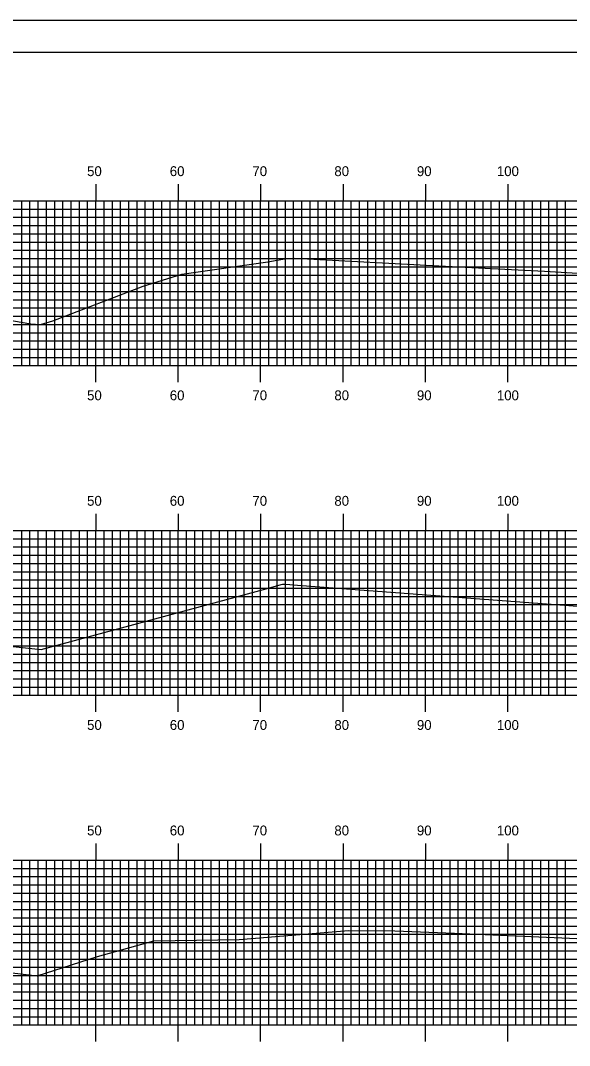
# Model space of a CAD drawing. Extents: x 841388 to 841731, y 363538 to 363758.
# Drawn here: x 841594.7 to 841661.4, y 363633.2 to 363757.6 of the extents above; entities that cross this region are included whole.
import ezdxf

# ---------------------------------------------------------------- set-up
doc = ezdxf.new("R2010")
doc.units = 0
for name, color, linetype in [('BORDER', 7, 'Continuous'), ('H_V ANNOTATION', 7, 'Continuous'), ('MAJOR', 7, 'Continuous'), ('MINOR', 7, 'Continuous'), ('PLOT BOUNDARY', 7, 'Continuous'), ('S_Roadway_Centerline', 7, 'Continuous')]:
    doc.layers.add(name, color=color, linetype=linetype)

msp = doc.modelspace()

# ---------------------------------------------------------------- linework, layer by layer
at = {"layer": 'BORDER'}
msp.add_lwpolyline([(841404.26, 363543.72), (841724.26, 363543.72), (841724.26, 363753.72), (841404.26, 363753.72)], close=True, dxfattribs=at)
at = {"layer": 'MAJOR'}
for p, q in [((841603.86, 363737.73), (841603.86, 363735.72)), ((841613.86, 363737.73), (841613.86, 363735.72)), ((841623.86, 363737.73), (841623.86, 363735.72)), ((841633.86, 363737.73), (841633.86, 363735.72)), ((841643.86, 363737.73), (841643.86, 363735.72)), ((841653.86, 363737.73), (841653.86, 363735.72)), ((841413.86, 363735.72), (841693.86, 363735.72)), ((841413.86, 363735.72), (841693.86, 363735.72)), ((841603.86, 363715.72), (841603.86, 363735.72)), ((841613.86, 363715.72), (841613.86, 363735.72)), ((841623.86, 363715.72), (841623.86, 363735.72)), ((841633.86, 363715.72), (841633.86, 363735.72)), ((841643.86, 363715.72), (841643.86, 363735.72)), ((841653.86, 363715.72), (841653.86, 363735.72)), ((841413.86, 363730.72), (841693.86, 363730.72)), ((841413.86, 363725.72), (841693.86, 363725.72)), ((841413.86, 363720.72), (841693.86, 363720.72)), ((841413.86, 363715.72), (841693.86, 363715.72)), ((841413.86, 363715.72), (841693.86, 363715.72)), ((841603.86, 363713.72), (841603.86, 363715.72)), ((841613.86, 363713.72), (841613.86, 363715.72)), ((841623.86, 363713.72), (841623.86, 363715.72)), ((841633.86, 363713.72), (841633.86, 363715.72)), ((841643.86, 363713.72), (841643.86, 363715.72)), ((841653.86, 363713.72), (841653.86, 363715.72)), ((841603.86, 363697.73), (841603.86, 363695.72)), ((841613.86, 363697.73), (841613.86, 363695.72)), ((841623.86, 363697.73), (841623.86, 363695.72)), ((841633.86, 363697.73), (841633.86, 363695.72)), ((841643.86, 363697.73), (841643.86, 363695.72)), ((841653.86, 363697.73), (841653.86, 363695.72)), ((841413.86, 363695.72), (841693.86, 363695.72)), ((841413.86, 363695.72), (841693.86, 363695.72)), ((841603.86, 363675.72), (841603.86, 363695.72)), ((841613.86, 363675.72), (841613.86, 363695.72)), ((841623.86, 363675.72), (841623.86, 363695.72)), ((841633.86, 363675.72), (841633.86, 363695.72)), ((841643.86, 363675.72), (841643.86, 363695.72)), ((841653.86, 363675.72), (841653.86, 363695.72)), ((841413.86, 363690.72), (841693.86, 363690.72)), ((841413.86, 363685.72), (841693.86, 363685.72)), ((841413.86, 363680.72), (841693.86, 363680.72)), ((841413.86, 363675.72), (841693.86, 363675.72)), ((841413.86, 363675.72), (841693.86, 363675.72)), ((841603.86, 363673.72), (841603.86, 363675.72)), ((841613.86, 363673.72), (841613.86, 363675.72)), ((841623.86, 363673.72), (841623.86, 363675.72)), ((841633.86, 363673.72), (841633.86, 363675.72)), ((841643.86, 363673.72), (841643.86, 363675.72)), ((841653.86, 363673.72), (841653.86, 363675.72)), ((841603.86, 363657.73), (841603.86, 363655.72)), ((841613.86, 363657.73), (841613.86, 363655.72)), ((841623.86, 363657.73), (841623.86, 363655.72)), ((841633.86, 363657.73), (841633.86, 363655.72)), ((841643.86, 363657.73), (841643.86, 363655.72)), ((841653.86, 363657.73), (841653.86, 363655.72)), ((841413.86, 363655.72), (841693.86, 363655.72)), ((841413.86, 363655.72), (841693.86, 363655.72)), ((841603.86, 363635.72), (841603.86, 363655.72)), ((841613.86, 363635.72), (841613.86, 363655.72)), ((841623.86, 363635.72), (841623.86, 363655.72)), ((841633.86, 363635.72), (841633.86, 363655.72)), ((841643.86, 363635.72), (841643.86, 363655.72)), ((841653.86, 363635.72), (841653.86, 363655.72)), ((841413.86, 363650.72), (841693.86, 363650.72)), ((841413.86, 363645.72), (841693.86, 363645.72)), ((841413.86, 363640.72), (841693.86, 363640.72)), ((841413.86, 363635.72), (841693.86, 363635.72)), ((841413.86, 363635.72), (841693.86, 363635.72)), ((841603.86, 363633.72), (841603.86, 363635.72)), ((841613.86, 363633.72), (841613.86, 363635.72)), ((841623.86, 363633.72), (841623.86, 363635.72)), ((841633.86, 363633.72), (841633.86, 363635.72)), ((841643.86, 363633.72), (841643.86, 363635.72)), ((841653.86, 363633.72), (841653.86, 363635.72))]:
    msp.add_line(p, q, dxfattribs=at)
at = {"layer": 'MINOR'}
for p, q in [((841594.86, 363715.72), (841594.86, 363735.72)), ((841595.86, 363715.72), (841595.86, 363735.72)), ((841596.86, 363715.72), (841596.86, 363735.72)), ((841597.86, 363715.72), (841597.86, 363735.72)), ((841598.86, 363715.72), (841598.86, 363735.72)), ((841599.86, 363715.72), (841599.86, 363735.72)), ((841600.86, 363715.72), (841600.86, 363735.72)), ((841601.86, 363715.72), (841601.86, 363735.72)), ((841602.86, 363715.72), (841602.86, 363735.72)), ((841604.86, 363715.72), (841604.86, 363735.72)), ((841605.86, 363715.72), (841605.86, 363735.72)), ((841606.86, 363715.72), (841606.86, 363735.72)), ((841607.86, 363715.72), (841607.86, 363735.72)), ((841608.86, 363715.72), (841608.86, 363735.72)), ((841609.86, 363715.72), (841609.86, 363735.72)), ((841610.86, 363715.72), (841610.86, 363735.72)), ((841611.86, 363715.72), (841611.86, 363735.72)), ((841612.86, 363715.72), (841612.86, 363735.72)), ((841614.86, 363715.72), (841614.86, 363735.72)), ((841615.86, 363715.72), (841615.86, 363735.72)), ((841616.86, 363715.72), (841616.86, 363735.72)), ((841617.86, 363715.72), (841617.86, 363735.72)), ((841618.86, 363715.72), (841618.86, 363735.72)), ((841619.86, 363715.72), (841619.86, 363735.72)), ((841620.86, 363715.72), (841620.86, 363735.72)), ((841621.86, 363715.72), (841621.86, 363735.72)), ((841622.86, 363715.72), (841622.86, 363735.72)), ((841624.86, 363715.72), (841624.86, 363735.72)), ((841625.86, 363715.72), (841625.86, 363735.72)), ((841626.86, 363715.72), (841626.86, 363735.72)), ((841627.86, 363715.72), (841627.86, 363735.72)), ((841628.86, 363715.72), (841628.86, 363735.72)), ((841629.86, 363715.72), (841629.86, 363735.72)), ((841630.86, 363715.72), (841630.86, 363735.72)), ((841631.86, 363715.72), (841631.86, 363735.72)), ((841632.86, 363715.72), (841632.86, 363735.72)), ((841634.86, 363715.72), (841634.86, 363735.72)), ((841635.86, 363715.72), (841635.86, 363735.72)), ((841636.86, 363715.72), (841636.86, 363735.72)), ((841637.86, 363715.72), (841637.86, 363735.72)), ((841638.86, 363715.72), (841638.86, 363735.72)), ((841639.86, 363715.72), (841639.86, 363735.72)), ((841640.86, 363715.72), (841640.86, 363735.72)), ((841641.86, 363715.72), (841641.86, 363735.72)), ((841642.86, 363715.72), (841642.86, 363735.72)), ((841644.86, 363715.72), (841644.86, 363735.72)), ((841645.86, 363715.72), (841645.86, 363735.72)), ((841646.86, 363715.72), (841646.86, 363735.72)), ((841647.86, 363715.72), (841647.86, 363735.72)), ((841648.86, 363715.72), (841648.86, 363735.72)), ((841649.86, 363715.72), (841649.86, 363735.72)), ((841650.86, 363715.72), (841650.86, 363735.72)), ((841651.86, 363715.72), (841651.86, 363735.72)), ((841652.86, 363715.72), (841652.86, 363735.72)), ((841654.86, 363715.72), (841654.86, 363735.72)), ((841655.86, 363715.72), (841655.86, 363735.72)), ((841656.86, 363715.72), (841656.86, 363735.72)), ((841657.86, 363715.72), (841657.86, 363735.72)), ((841658.86, 363715.72), (841658.86, 363735.72)), ((841659.86, 363715.72), (841659.86, 363735.72)), ((841660.86, 363715.72), (841660.86, 363735.72)), ((841413.86, 363734.72), (841693.86, 363734.72)), ((841413.86, 363733.72), (841693.86, 363733.72)), ((841413.86, 363732.72), (841693.86, 363732.72)), ((841413.86, 363731.72), (841693.86, 363731.72)), ((841413.86, 363729.72), (841693.86, 363729.72)), ((841413.86, 363728.72), (841693.86, 363728.72)), ((841413.86, 363727.72), (841693.86, 363727.72)), ((841413.86, 363726.72), (841693.86, 363726.72)), ((841413.86, 363724.72), (841693.86, 363724.72)), ((841413.86, 363723.72), (841693.86, 363723.72)), ((841413.86, 363722.72), (841693.86, 363722.72)), ((841413.86, 363721.72), (841693.86, 363721.72)), ((841413.86, 363719.72), (841693.86, 363719.72)), ((841413.86, 363718.72), (841693.86, 363718.72)), ((841413.86, 363717.72), (841693.86, 363717.72)), ((841413.86, 363716.72), (841693.86, 363716.72)), ((841594.86, 363675.72), (841594.86, 363695.72)), ((841595.86, 363675.72), (841595.86, 363695.72)), ((841596.86, 363675.72), (841596.86, 363695.72)), ((841597.86, 363675.72), (841597.86, 363695.72)), ((841598.86, 363675.72), (841598.86, 363695.72)), ((841599.86, 363675.72), (841599.86, 363695.72)), ((841600.86, 363675.72), (841600.86, 363695.72)), ((841601.86, 363675.72), (841601.86, 363695.72)), ((841602.86, 363675.72), (841602.86, 363695.72)), ((841604.86, 363675.72), (841604.86, 363695.72)), ((841605.86, 363675.72), (841605.86, 363695.72)), ((841606.86, 363675.72), (841606.86, 363695.72)), ((841607.86, 363675.72), (841607.86, 363695.72)), ((841608.86, 363675.72), (841608.86, 363695.72)), ((841609.86, 363675.72), (841609.86, 363695.72)), ((841610.86, 363675.72), (841610.86, 363695.72)), ((841611.86, 363675.72), (841611.86, 363695.72)), ((841612.86, 363675.72), (841612.86, 363695.72)), ((841614.86, 363675.72), (841614.86, 363695.72)), ((841615.86, 363675.72), (841615.86, 363695.72)), ((841616.86, 363675.72), (841616.86, 363695.72)), ((841617.86, 363675.72), (841617.86, 363695.72)), ((841618.86, 363675.72), (841618.86, 363695.72)), ((841619.86, 363675.72), (841619.86, 363695.72)), ((841620.86, 363675.72), (841620.86, 363695.72)), ((841621.86, 363675.72), (841621.86, 363695.72)), ((841622.86, 363675.72), (841622.86, 363695.72)), ((841624.86, 363675.72), (841624.86, 363695.72)), ((841625.86, 363675.72), (841625.86, 363695.72)), ((841626.86, 363675.72), (841626.86, 363695.72)), ((841627.86, 363675.72), (841627.86, 363695.72)), ((841628.86, 363675.72), (841628.86, 363695.72)), ((841629.86, 363675.72), (841629.86, 363695.72)), ((841630.86, 363675.72), (841630.86, 363695.72)), ((841631.86, 363675.72), (841631.86, 363695.72)), ((841632.86, 363675.72), (841632.86, 363695.72)), ((841634.86, 363675.72), (841634.86, 363695.72)), ((841635.86, 363675.72), (841635.86, 363695.72)), ((841636.86, 363675.72), (841636.86, 363695.72)), ((841637.86, 363675.72), (841637.86, 363695.72)), ((841638.86, 363675.72), (841638.86, 363695.72)), ((841639.86, 363675.72), (841639.86, 363695.72)), ((841640.86, 363675.72), (841640.86, 363695.72)), ((841641.86, 363675.72), (841641.86, 363695.72)), ((841642.86, 363675.72), (841642.86, 363695.72)), ((841644.86, 363675.72), (841644.86, 363695.72)), ((841645.86, 363675.72), (841645.86, 363695.72)), ((841646.86, 363675.72), (841646.86, 363695.72)), ((841647.86, 363675.72), (841647.86, 363695.72)), ((841648.86, 363675.72), (841648.86, 363695.72)), ((841649.86, 363675.72), (841649.86, 363695.72)), ((841650.86, 363675.72), (841650.86, 363695.72)), ((841651.86, 363675.72), (841651.86, 363695.72)), ((841652.86, 363675.72), (841652.86, 363695.72)), ((841654.86, 363675.72), (841654.86, 363695.72)), ((841655.86, 363675.72), (841655.86, 363695.72)), ((841656.86, 363675.72), (841656.86, 363695.72)), ((841657.86, 363675.72), (841657.86, 363695.72)), ((841658.86, 363675.72), (841658.86, 363695.72)), ((841659.86, 363675.72), (841659.86, 363695.72)), ((841660.86, 363675.72), (841660.86, 363695.72)), ((841413.86, 363694.72), (841693.86, 363694.72)), ((841413.86, 363693.72), (841693.86, 363693.72)), ((841413.86, 363692.72), (841693.86, 363692.72)), ((841413.86, 363691.72), (841693.86, 363691.72)), ((841413.86, 363689.72), (841693.86, 363689.72)), ((841413.86, 363688.72), (841693.86, 363688.72)), ((841413.86, 363687.72), (841693.86, 363687.72)), ((841413.86, 363686.72), (841693.86, 363686.72)), ((841413.86, 363684.72), (841693.86, 363684.72)), ((841413.86, 363683.72), (841693.86, 363683.72)), ((841413.86, 363682.72), (841693.86, 363682.72)), ((841413.86, 363681.72), (841693.86, 363681.72)), ((841413.86, 363679.72), (841693.86, 363679.72)), ((841413.86, 363678.72), (841693.86, 363678.72)), ((841413.86, 363677.72), (841693.86, 363677.72)), ((841413.86, 363676.72), (841693.86, 363676.72)), ((841594.86, 363635.72), (841594.86, 363655.72)), ((841595.86, 363635.72), (841595.86, 363655.72)), ((841596.86, 363635.72), (841596.86, 363655.72)), ((841597.86, 363635.72), (841597.86, 363655.72)), ((841598.86, 363635.72), (841598.86, 363655.72)), ((841599.86, 363635.72), (841599.86, 363655.72)), ((841600.86, 363635.72), (841600.86, 363655.72)), ((841601.86, 363635.72), (841601.86, 363655.72)), ((841602.86, 363635.72), (841602.86, 363655.72)), ((841604.86, 363635.72), (841604.86, 363655.72)), ((841605.86, 363635.72), (841605.86, 363655.72)), ((841606.86, 363635.72), (841606.86, 363655.72)), ((841607.86, 363635.72), (841607.86, 363655.72)), ((841608.86, 363635.72), (841608.86, 363655.72)), ((841609.86, 363635.72), (841609.86, 363655.72)), ((841610.86, 363635.72), (841610.86, 363655.72)), ((841611.86, 363635.72), (841611.86, 363655.72)), ((841612.86, 363635.72), (841612.86, 363655.72)), ((841614.86, 363635.72), (841614.86, 363655.72)), ((841615.86, 363635.72), (841615.86, 363655.72)), ((841616.86, 363635.72), (841616.86, 363655.72)), ((841617.86, 363635.72), (841617.86, 363655.72)), ((841618.86, 363635.72), (841618.86, 363655.72)), ((841619.86, 363635.72), (841619.86, 363655.72)), ((841620.86, 363635.72), (841620.86, 363655.72)), ((841621.86, 363635.72), (841621.86, 363655.72)), ((841622.86, 363635.72), (841622.86, 363655.72)), ((841624.86, 363635.72), (841624.86, 363655.72)), ((841625.86, 363635.72), (841625.86, 363655.72)), ((841626.86, 363635.72), (841626.86, 363655.72)), ((841627.86, 363635.72), (841627.86, 363655.72)), ((841628.86, 363635.72), (841628.86, 363655.72)), ((841629.86, 363635.72), (841629.86, 363655.72)), ((841630.86, 363635.72), (841630.86, 363655.72)), ((841631.86, 363635.72), (841631.86, 363655.72)), ((841632.86, 363635.72), (841632.86, 363655.72)), ((841634.86, 363635.72), (841634.86, 363655.72)), ((841635.86, 363635.72), (841635.86, 363655.72)), ((841636.86, 363635.72), (841636.86, 363655.72)), ((841637.86, 363635.72), (841637.86, 363655.72)), ((841638.86, 363635.72), (841638.86, 363655.72)), ((841639.86, 363635.72), (841639.86, 363655.72)), ((841640.86, 363635.72), (841640.86, 363655.72)), ((841641.86, 363635.72), (841641.86, 363655.72)), ((841642.86, 363635.72), (841642.86, 363655.72)), ((841644.86, 363635.72), (841644.86, 363655.72)), ((841645.86, 363635.72), (841645.86, 363655.72)), ((841646.86, 363635.72), (841646.86, 363655.72)), ((841647.86, 363635.72), (841647.86, 363655.72)), ((841648.86, 363635.72), (841648.86, 363655.72)), ((841649.86, 363635.72), (841649.86, 363655.72)), ((841650.86, 363635.72), (841650.86, 363655.72)), ((841651.86, 363635.72), (841651.86, 363655.72)), ((841652.86, 363635.72), (841652.86, 363655.72)), ((841654.86, 363635.72), (841654.86, 363655.72)), ((841655.86, 363635.72), (841655.86, 363655.72)), ((841656.86, 363635.72), (841656.86, 363655.72)), ((841657.86, 363635.72), (841657.86, 363655.72)), ((841658.86, 363635.72), (841658.86, 363655.72)), ((841659.86, 363635.72), (841659.86, 363655.72)), ((841660.86, 363635.72), (841660.86, 363655.72)), ((841413.86, 363654.72), (841693.86, 363654.72)), ((841413.86, 363653.72), (841693.86, 363653.72)), ((841413.86, 363652.72), (841693.86, 363652.72)), ((841413.86, 363651.72), (841693.86, 363651.72)), ((841413.86, 363649.72), (841693.86, 363649.72)), ((841413.86, 363648.72), (841693.86, 363648.72)), ((841413.86, 363647.72), (841693.86, 363647.72)), ((841413.86, 363646.72), (841693.86, 363646.72)), ((841413.86, 363644.72), (841693.86, 363644.72)), ((841413.86, 363643.72), (841693.86, 363643.72)), ((841413.86, 363642.72), (841693.86, 363642.72)), ((841413.86, 363641.72), (841693.86, 363641.72)), ((841413.86, 363639.72), (841693.86, 363639.72)), ((841413.86, 363638.72), (841693.86, 363638.72)), ((841413.86, 363637.72), (841693.86, 363637.72)), ((841413.86, 363636.72), (841693.86, 363636.72))]:
    msp.add_line(p, q, dxfattribs=at)
at = {"layer": 'PLOT BOUNDARY'}
msp.add_lwpolyline([(841388.07, 363537.6), (841728.07, 363537.6), (841728.07, 363757.6), (841388.07, 363757.6)], close=True, dxfattribs=at)
at = {"layer": 'S_Roadway_Centerline'}
for points in [[(841584.47, 363722.78), (841595.98, 363720.78), (841597.14, 363720.73), (841598.63, 363721.14), (841609.59, 363725.38), (841614.28, 363726.83), (841624.75, 363728.3), (841627.01, 363728.73), (841627.97, 363728.77), (841628.78, 363728.71), (841645.49, 363727.83), (841658.34, 363727.19), (841663, 363726.92), (841665.12, 363726.83), (841681.82, 363726.05), (841691.88, 363725.55), (841693.86, 363725.46)], [(841593.41, 363681.67), (841597.22, 363681.28), (841624.8, 363688.73), (841626.36, 363689.18), (841626.52, 363689.21), (841626.72, 363689.2), (841626.9, 363689.19), (841628.33, 363689.1), (841666.14, 363686.25), (841679.49, 363685.69), (841685.75, 363685.46), (841693.86, 363685.27)], [(841593.7, 363642.05), (841596.73, 363641.67), (841604.05, 363644.03), (841610.89, 363645.94), (841621.24, 363646.08), (841634.53, 363647.18), (841640.16, 363647.13), (841647.39, 363646.85), (841676.2, 363645.61), (841677.3, 363645.62), (841689.52, 363645.48), (841693.86, 363645.3)]]:
    msp.add_lwpolyline(points, dxfattribs=at)

# ---------------------------------------------------------------- texts
at = {"layer": 'H_V ANNOTATION'}
for s, p in [('50', (841602.79, 363738.72)), ('60', (841612.83, 363738.72)), ('70', (841622.86, 363738.72)), ('80', (841632.81, 363738.72)), ('90', (841642.83, 363738.72)), ('100', (841652.54, 363738.72)), ('50', (841602.79, 363711.52)), ('60', (841612.83, 363711.52)), ('70', (841622.86, 363711.52)), ('80', (841632.81, 363711.52)), ('90', (841642.83, 363711.52)), ('100', (841652.54, 363711.52)), ('50', (841602.79, 363698.72)), ('60', (841612.83, 363698.72)), ('70', (841622.86, 363698.72)), ('80', (841632.81, 363698.72)), ('90', (841642.83, 363698.72)), ('100', (841652.54, 363698.72)), ('50', (841602.79, 363671.52)), ('60', (841612.83, 363671.52)), ('70', (841622.86, 363671.52)), ('80', (841632.81, 363671.52)), ('90', (841642.83, 363671.52)), ('100', (841652.54, 363671.52)), ('50', (841602.79, 363658.72)), ('60', (841612.83, 363658.72)), ('70', (841622.86, 363658.72)), ('80', (841632.81, 363658.72)), ('90', (841642.83, 363658.72)), ('100', (841652.54, 363658.72))]:
    msp.add_text(s, height=1.2, dxfattribs=at).set_placement(p)

doc.saveas('drawing.dxf')
